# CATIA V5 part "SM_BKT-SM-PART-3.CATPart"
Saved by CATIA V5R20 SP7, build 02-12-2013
Part number: SM_BKT
Bounding box of the stored display mesh (mm): x 0 to 139.973, y -20 to 228.383, z 0 to 46
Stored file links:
  C:\Users\CAS-\Desktop\Exercise Files\SM_BKT-SM-PART-3.CATPart
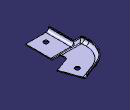
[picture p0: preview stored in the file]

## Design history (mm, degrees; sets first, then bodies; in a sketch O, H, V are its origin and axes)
Set1 "CONST_GEO"
  Point1: type OnCurve, Support Sketch1, Length 10
Set2 "Inputs"
  Sketch1 "Flange Sketch" on xy-plane, origin (0, 0, 0), H (1, 0, 0), V (0, 1, 0)
    point P1 (0, -20)
    line L1 (0, -20) -> (0, 125)
    arc A1 centre (90, 125) radius 90 from (0, 125) to (59.2182, 209.5723) cw
    point P3 (90, 125)
    line L2 (59.2182, 209.5723) -> (120.2982, 231.8036)
    radius A1 = 90
    distance H P3 = 125
    angle L1 L2 = 110
    length L2 = 65
    distance H P1 = 20
    coincidence: P1 V
    vertical: L1 V
    tangency: A1 L1, A1 L2
  Sketch2 "Main Body Sketch" on yz-plane, origin (0, 0, 0), H (0, 1, 0), V (0, 0, 1)
    point P1 (-20, 0)
    line L1 (-20, 0) -> (75, 0)
    point P2 (75, 0)
    line L2 (75, 0) -> (105, 30)
    line L3 (105, 30) -> (280, 30)
    reference intersected line E1 through (0, 0) direction (0, 1) from zx-plane
    distance V P1 = 20
    angle L1 L2 = 45
    distance L1 L3 = 30
    distance E1 P2 = 75
    length L3 = 175
    horizontal: L1 H, L3 H
    coincidence: H L1
Set3 "Spliting Elements"
  Plane1: type Normal, Curve Sketch1, RefPoint Point1
  Offset1: Offset Extrude2, Length 85
  Extract1: ExtractElem edge [face of Fillet3 | face of Extrude2 from Sketch1.L2]
  Extract2: ExtractElem edge [face of Fillet3 | face of Extrude2 from Sketch1.L1]
  Join1: Elements (Extract2; Extract1)
  CurvePar1: Offset Join1, Offset2 0, Offset1 3, Support Extrude2
  Cylinder1: Direction xy-plane, Length1 40, Length2 40, Radius 8, Center Point2
  Cylinder2: Direction xy-plane, Length1 40, Length2 40, Radius 8, Center Point3
Set4 "Split"
  Split1: ToCut Fillet3, Cutting (CurvePar1; Plane1; Offset1; Cylinder1; Cylinder2)
Set5 "Operations"
  Extrude1 "Slab-1": Element1 Sketch2, Lim1 209, Lim2 87
  Extrude2 "Slab-2": Element1 Sketch1, Lim1 209, Lim2 87
  Fillet1: radius 13, on edge [face of Extrude1 from Sketch2.L2 | face of Extrude1 from Sketch2.L1]
  Fillet2: radius 10, on edge [face of Extrude1 from Sketch2.L3 | face of Extrude1 from Sketch2.L2]
  Fillet3 "Main-Body": type BiTangent, Element1 Extrude2, Element2 Fillet2, Radius 13
  Offset2: Offset Extrude2, Length 42.5
  Intersect1: ToIntersect1 Fillet3, ToIntersect2 Offset2
  Point2: type OnCurve, Support Intersect1, Length 30
  Intersect2: ToIntersect1 Intersect1, ToIntersect2 Plane1
  Point3: type OnCurve, Support Intersect1, Length 30, RefPoint Intersect2
Body1 (main body)
  ThickSurface1: BotOffset 0, Surface Split1, TopOffset 3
